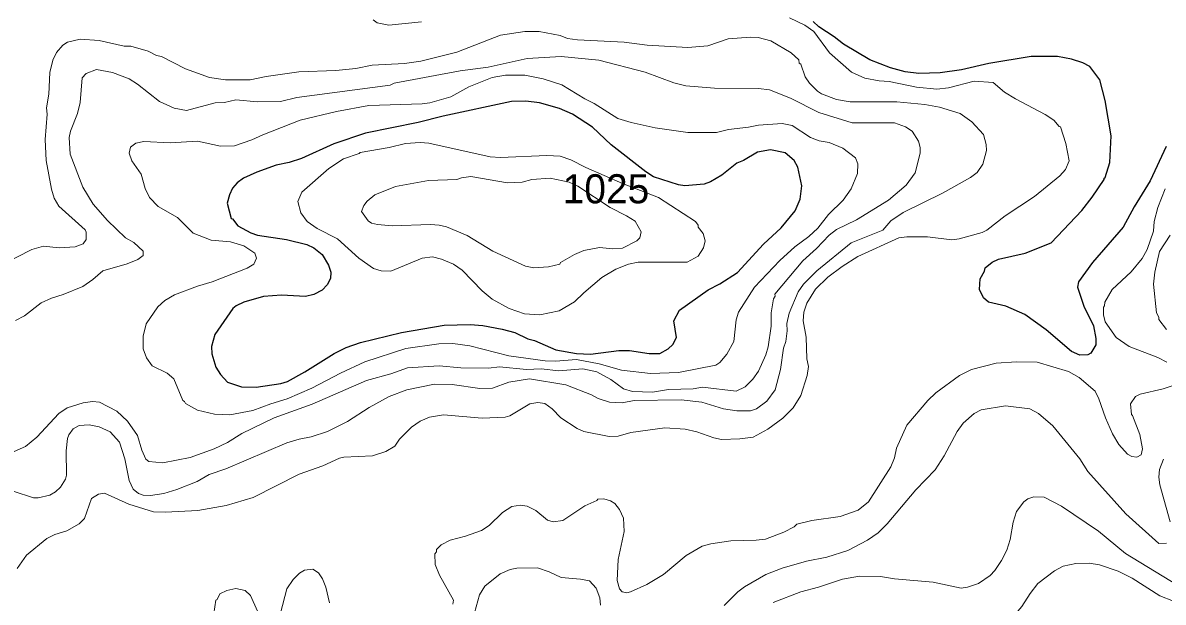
# Model space of a CAD drawing. Extents: x 447.8 to 473.9, y 7733.1 to 7760.8.
# Drawn here: x 469.176 to 472.312, y 7755.382 to 7756.976 of the extents above; entities that cross this region are included whole.
import ezdxf

# ---------------------------------------------------------------- set-up
doc = ezdxf.new("R2010")
doc.units = 0
doc.header["$LTSCALE"] = 0.032
doc.layers.add('1', color=7, linetype='Continuous', lineweight=25)
doc.layers.add('2', color=7, linetype='Continuous', lineweight=13)
doc.layers.add('21', color=7, linetype='Continuous')

msp = doc.modelspace()

# ---------------------------------------------------------------- linework, layer by layer
at = {"layer": '1'}
for points in [[(472.0594, 7756.0718), (471.9898, 7756.1313), (471.9307, 7756.1734), (471.8785, 7756.1964), (471.8309, 7756.2068), (471.8175, 7756.2187), (471.8061, 7756.2423), (471.8084, 7756.2715), (471.8203, 7756.2928), (471.8224, 7756.3018), (471.8413, 7756.3175), (471.8586, 7756.3254), (471.9318, 7756.3423), (472.0034, 7756.3704), (472.0876, 7756.4589), (472.1165, 7756.4956), (472.1489, 7756.5444), (472.1492, 7756.5483), (472.1523, 7756.5496), (472.1652, 7756.5917), (472.1683, 7756.665), (472.1521, 7756.7616), (472.1376, 7756.8188), (472.1101, 7756.855), (472.0906, 7756.8653), (472.0598, 7756.8759), (472.0212, 7756.8826), (471.9484, 7756.8826), (471.8324, 7756.8633), (471.7567, 7756.8459), (471.6983, 7756.8377), (471.6393, 7756.8363), (471.6021, 7756.8411), (471.5614, 7756.8513), (471.5048, 7756.8738), (471.4325, 7756.9169), (471.4068, 7756.9372), (471.3648, 7756.9641), (471.3489, 7756.9792)], [(470.9815, 7756.1847), (471.06, 7756.2408), (471.0926, 7756.2574), (471.141, 7756.289), (471.213, 7756.3666), (471.261, 7756.4114), (471.2996, 7756.4581), (471.3138, 7756.4908), (471.3177, 7756.5275), (471.3068, 7756.5785), (471.2973, 7756.597), (471.2721, 7756.6178), (471.232, 7756.6261), (471.1964, 7756.6198), (471.1578, 7756.5967), (471.1395, 7756.5894), (471.0976, 7756.5568), (471.0666, 7756.5378), (471.049, 7756.5315), (470.9961, 7756.5268), (470.9784, 7756.53), (470.9104, 7756.5519), (470.889, 7756.5655), (470.7939, 7756.6396), (470.7422, 7756.6882), (470.687, 7756.7247), (470.652, 7756.7399), (470.5969, 7756.7553), (470.5591, 7756.76), (470.5199, 7756.7592), (470.3315, 7756.7192), (470.2629, 7756.7012), (470.118, 7756.6722), (470.031, 7756.6429), (469.9424, 7756.6019), (469.9082, 7756.591), (469.8726, 7756.5836), (469.8194, 7756.5643), (469.7831, 7756.5478), (469.7657, 7756.5353), (469.7524, 7756.5205), (469.7441, 7756.5027), (469.7381, 7756.4795), (469.7489, 7756.4376), (469.7527, 7756.4365), (469.7671, 7756.4167), (469.8033, 7756.3979), (469.8215, 7756.3918), (469.9013, 7756.3797), (469.9572, 7756.3657), (469.9765, 7756.3562), (469.9992, 7756.3384), (470.0169, 7756.3085), (470.0232, 7756.2895), (470.0224, 7756.2722), (470.0129, 7756.2545), (469.9987, 7756.2402), (469.9765, 7756.2285), (469.953, 7756.223), (469.8872, 7756.2261), (469.8381, 7756.2225), (469.7837, 7756.207), (469.7623, 7756.1967), (469.7532, 7756.1893), (469.7036, 7756.1182), (469.695, 7756.0851), (469.6954, 7756.0654), (469.7068, 7756.0279), (469.7196, 7756.0077), (469.7389, 7755.9868), (469.7768, 7755.9744), (469.8172, 7755.9729), (469.8858, 7755.9834), (469.9033, 7755.9891), (469.9511, 7756.0153), (470.0316, 7756.066), (470.0646, 7756.0826), (470.1043, 7756.0964), (470.2176, 7756.1236), (470.3342, 7756.1438), (470.4056, 7756.146), (470.4405, 7756.1428), (470.4938, 7756.1331), (470.5287, 7756.1234), (470.5648, 7756.1061), (470.5832, 7756.1018), (470.6413, 7756.076), (470.6986, 7756.0658), (470.7371, 7756.0643), (470.8144, 7756.0739), (470.8445, 7756.0738), (470.8983, 7756.0659), (470.9271, 7756.0659), (470.9507, 7756.0787), (470.9633, 7756.0905)], [(472.3202, 7756.6351), (472.2757, 7756.5412), (472.2317, 7756.4693), (472.2016, 7756.4137), (472.1176, 7756.3165), (472.0787, 7756.2629), (472.0763, 7756.2481), (472.0931, 7756.1963), (472.1201, 7756.1423), (472.1266, 7756.1071)], [(470.9633, 7756.0905), (470.973, 7756.1102), (470.966, 7756.1556), (470.9815, 7756.1847)], [(472.1266, 7756.1071), (472.1264, 7756.0901), (472.1129, 7756.0667), (472.1048, 7756.0626), (472.0821, 7756.0611), (472.0594, 7756.0718)]]:
    msp.add_lwpolyline(points, dxfattribs=at)
at = {"layer": '2'}
for points in [[(470.2723, 7756.9786), (470.1825, 7756.9693), (470.1502, 7756.9755), (470.1389, 7756.9835)], [(472.0289, 7756.6891), (472.0255, 7756.6899), (472.0109, 7756.7079), (471.9868, 7756.7233), (471.9052, 7756.766), (471.8756, 7756.7852), (471.8442, 7756.8111), (471.7922, 7756.8146), (471.7216, 7756.7971), (471.6894, 7756.793), (471.6337, 7756.7986), (471.5579, 7756.8145), (471.5306, 7756.8155), (471.4915, 7756.8232), (471.4547, 7756.8396), (471.3939, 7756.8934), (471.3509, 7756.9521), (471.326, 7756.9688), (471.2842, 7756.9892)], [(469.1181, 7756.3099), (469.2011, 7756.3521), (469.2329, 7756.3608), (469.2759, 7756.3561), (469.32, 7756.359), (469.3418, 7756.3672), (469.3497, 7756.3791), (469.3501, 7756.3999), (469.3474, 7756.4064), (469.2754, 7756.4716), (469.2622, 7756.4935), (469.2545, 7756.5175), (469.2402, 7756.597), (469.2378, 7756.6544), (469.2426, 7756.7247), (469.241, 7756.7416), (469.2473, 7756.7797), (469.2506, 7756.8393), (469.2581, 7756.8725), (469.2684, 7756.8942), (469.2861, 7756.9141), (469.2989, 7756.9223), (469.3334, 7756.9308), (469.3861, 7756.9268), (469.4546, 7756.9114), (469.4726, 7756.9115), (469.5204, 7756.8975), (469.5437, 7756.886), (469.5569, 7756.8826), (469.6236, 7756.8493), (469.6895, 7756.825), (469.7336, 7756.8186), (469.8011, 7756.8186), (469.845, 7756.8281), (469.9348, 7756.841), (470.0368, 7756.8443), (470.0919, 7756.8498), (470.1368, 7756.8586), (470.2258, 7756.8633), (470.2706, 7756.8696), (470.3689, 7756.8946), (470.4893, 7756.9413), (470.5559, 7756.9517), (470.5953, 7756.9517), (470.6533, 7756.9404), (470.6736, 7756.9321), (470.7011, 7756.9284), (470.8296, 7756.9219), (470.8931, 7756.914), (471.0049, 7756.9076), (471.0595, 7756.9125), (471.1152, 7756.9318), (471.1769, 7756.9363), (471.1981, 7756.9348), (471.2323, 7756.9258), (471.2885, 7756.8929), (471.3097, 7756.8738), (471.3107, 7756.8646), (471.3149, 7756.8619), (471.3273, 7756.8268), (471.339, 7756.8094), (471.3606, 7756.7874), (471.3718, 7756.7799), (471.4129, 7756.7649), (471.4511, 7756.7585), (471.579, 7756.7584), (471.6562, 7756.7505), (471.6967, 7756.7433), (471.7534, 7756.7262), (471.7857, 7756.7033), (471.8172, 7756.6683), (471.8252, 7756.6406), (471.8253, 7756.6243), (471.8159, 7756.5868), (471.7998, 7756.5639), (471.7822, 7756.5502), (471.705, 7756.5067), (471.5963, 7756.454), (471.5629, 7756.4311), (471.5406, 7756.4051), (471.4536, 7756.3706), (471.3593, 7756.2933), (471.3229, 7756.2569), (471.3076, 7756.2353), (471.2833, 7756.177), (471.277, 7756.1484), (471.2777, 7756.1285), (471.2737, 7756.0987), (471.2675, 7756.0802), (471.2594, 7756.0221), (471.2449, 7755.9657), (471.2217, 7755.9345), (471.1931, 7755.9133), (471.1771, 7755.908), (471.1388, 7755.908)], [(470.656, 7756.8827), (470.5623, 7756.8771), (470.4551, 7756.8536), (470.3789, 7756.8434), (470.1972, 7756.8092), (470.1857, 7756.8039), (469.9291, 7756.7705), (469.8845, 7756.7593), (469.821, 7756.7585), (469.7616, 7756.764), (469.7305, 7756.7559), (469.7046, 7756.7552), (469.6261, 7756.7344), (469.5917, 7756.741), (469.552, 7756.7588), (469.4916, 7756.8069), (469.4686, 7756.8217), (469.4226, 7756.839), (469.3781, 7756.8473), (469.35, 7756.8361), (469.3394, 7756.8243), (469.3339, 7756.756), (469.3265, 7756.7265), (469.3067, 7756.6776), (469.3035, 7756.6605), (469.306, 7756.614), (469.3405, 7756.5233), (469.3698, 7756.4765), (469.4091, 7756.4316), (469.4585, 7756.3845), (469.4812, 7756.3708), (469.5066, 7756.3476), (469.5068, 7756.3351), (469.492, 7756.3244), (469.4629, 7756.3122), (469.3961, 7756.2936), (469.3682, 7756.2692), (469.3406, 7756.2504), (469.2868, 7756.2283), (469.2544, 7756.2184), (469.226, 7756.2051), (469.1803, 7756.1694), (469.1554, 7756.1566)], [(471.0774, 7756.7954), (470.9993, 7756.8018), (470.9662, 7756.8104), (470.8868, 7756.8396), (470.7594, 7756.873), (470.656, 7756.8827)], [(471.4537, 7756.5187), (471.4708, 7756.5613), (471.4724, 7756.5876), (471.4659, 7756.6044), (471.4308, 7756.6309), (471.3931, 7756.646), (471.366, 7756.6512), (471.3414, 7756.6597), (471.2914, 7756.6927), (471.2637, 7756.6983), (471.1984, 7756.6943), (471.1716, 7756.6885), (471.1167, 7756.6822), (471.0833, 7756.6735), (471.0041, 7756.6735), (470.9143, 7756.6864), (470.8491, 7756.7011), (470.8123, 7756.7126), (470.7473, 7756.754), (470.7216, 7756.766), (470.6584, 7756.8048), (470.6065, 7756.8218), (470.5559, 7756.8313), (470.5035, 7756.8313), (470.4661, 7756.8249), (470.4019, 7756.7995), (470.3526, 7756.7715), (470.2947, 7756.7558), (470.2741, 7756.7529), (470.1272, 7756.748), (470.0381, 7756.732), (469.9387, 7756.708), (469.8358, 7756.6678), (469.8059, 7756.6534), (469.7584, 7756.6374), (469.7191, 7756.636), (469.6565, 7756.6502), (469.5811, 7756.6455), (469.5086, 7756.6486), (469.4869, 7756.6448), (469.4719, 7756.6331), (469.4687, 7756.6167), (469.4758, 7756.596), (469.5014, 7756.5588), (469.512, 7756.52), (469.5246, 7756.495), (469.548, 7756.4699), (469.6014, 7756.4404), (469.644, 7756.3966), (469.6939, 7756.3778), (469.7466, 7756.3735), (469.7838, 7756.3619), (469.8141, 7756.3421), (469.8181, 7756.3281), (469.8108, 7756.312), (469.7932, 7756.3003), (469.6965, 7756.2629), (469.6558, 7756.2509), (469.5932, 7756.2274), (469.5662, 7756.2115), (469.547, 7756.1939), (469.5154, 7756.1475), (469.5071, 7756.1138), (469.5073, 7756.0783), (469.5157, 7756.0541), (469.5312, 7756.0323), (469.5728, 7756.0121), (469.5909, 7755.9965), (469.6156, 7755.9363), (469.6208, 7755.9335), (469.6228, 7755.9281), (469.6566, 7755.9102), (469.7029, 7755.8988), (469.7455, 7755.8969), (469.8088, 7755.9088), (469.8575, 7755.9278), (469.9024, 7755.9414), (469.9707, 7755.9706), (470.0492, 7756.0115), (470.1165, 7756.0428), (470.2294, 7756.0794), (470.3195, 7756.0923), (470.3587, 7756.0931), (470.4052, 7756.0867), (470.5119, 7756.0595), (470.6119, 7756.0461), (470.6405, 7756.045), (470.6986, 7756.049), (470.7611, 7756.0378), (470.8219, 7756.0198), (470.9018, 7756.0105), (470.9784, 7756.0137), (471.0813, 7756.0339), (471.0923, 7756.0415), (471.112, 7756.0637)], [(469.1519, 7755.7963), (469.1832, 7755.8101), (469.2143, 7755.8356), (469.2752, 7755.9004), (469.2981, 7755.9164), (469.3423, 7755.9305), (469.3671, 7755.9337), (469.3868, 7755.932), (469.4344, 7755.9069), (469.4635, 7755.8794), (469.4913, 7755.84), (469.5029, 7755.8002), (469.5145, 7755.7749), (469.5225, 7755.7685), (469.5606, 7755.7653), (469.6357, 7755.7794), (469.7017, 7755.8032), (469.7389, 7755.821), (469.7783, 7755.8456), (469.8675, 7755.8886), (469.9716, 7755.9269), (470.1208, 7755.9912), (470.1878, 7756.0103), (470.234, 7756.0267), (470.3204, 7756.0323), (470.3805, 7756.0267), (470.4564, 7756.0258), (470.4862, 7756.029), (470.5612, 7756.0218), (470.6008, 7756.0241), (470.6498, 7756.0178), (470.7159, 7756.0233), (470.7543, 7756.0153), (470.7931, 7755.9943), (470.8274, 7755.9684), (470.8523, 7755.9613), (470.9073, 7755.9593), (470.9512, 7755.9672), (471.0188, 7755.9689), (471.045, 7755.9737), (471.1377, 7755.9625), (471.1618, 7755.9746), (471.1836, 7755.9951), (471.1992, 7756.017), (471.2192, 7756.0619), (471.2256, 7756.0843), (471.2336, 7756.1413), (471.2337, 7756.1777), (471.2402, 7756.2162), (471.2448, 7756.2232), (471.2436, 7756.2295), (471.321, 7756.3206), (471.3586, 7756.3543), (471.3935, 7756.3917), (471.4133, 7756.4073), (471.4687, 7756.4335), (471.5561, 7756.4875), (471.605, 7756.5286), (471.6299, 7756.5627), (471.6431, 7756.6174), (471.6435, 7756.6326), (471.6385, 7756.6502), (471.6217, 7756.6779), (471.6027, 7756.6894), (471.5732, 7756.7008), (471.4562, 7756.7008), (471.3645, 7756.729), (471.2869, 7756.7687), (471.2293, 7756.7908), (471.1991, 7756.7952), (471.0774, 7756.7954)], [(471.9581, 7756.4976), (472.0278, 7756.5546), (472.0428, 7756.5723), (472.0529, 7756.5958), (472.0441, 7756.6435), (472.0289, 7756.6891)], [(471.2575, 7756.3213), (471.2984, 7756.359), (471.3369, 7756.3876), (471.3617, 7756.4103), (471.3913, 7756.448), (471.4314, 7756.4873), (471.4537, 7756.5187)], [(472.3167, 7756.5187), (472.2966, 7756.4678), (472.287, 7756.4294), (472.2852, 7756.4026), (472.2676, 7756.3518), (472.2537, 7756.327), (472.2234, 7756.2901), (472.1712, 7756.2421), (472.151, 7756.2067), (472.1505, 7756.1972), (472.1475, 7756.1934), (472.1475, 7756.1721), (472.152, 7756.1526), (472.1827, 7756.11), (472.2179, 7756.0848), (472.2968, 7756.0545), (472.3219, 7756.042)], [(469.1603, 7755.4742), (469.1859, 7755.5114), (469.2416, 7755.5572), (469.2641, 7755.5683), (469.2967, 7755.5784), (469.331, 7755.5972), (469.3451, 7755.6116), (469.3646, 7755.6668), (469.3843, 7755.6789), (469.4009, 7755.6819), (469.467, 7755.6514), (469.5355, 7755.6305), (469.5687, 7755.6291), (469.6574, 7755.6338), (469.7351, 7755.6475), (469.8091, 7755.6693), (469.9358, 7755.7343), (470.0008, 7755.7564), (470.0468, 7755.7777), (470.0587, 7755.7807), (470.1371, 7755.7846), (470.1743, 7755.7959), (470.1989, 7755.8112), (470.2121, 7755.83), (470.2448, 7755.8632), (470.2686, 7755.8799), (470.2942, 7755.8903), (470.3324, 7755.8967), (470.4394, 7755.888), (470.5019, 7755.8903), (470.5155, 7755.8945), (470.5697, 7755.9278), (470.5924, 7755.9312), (470.6114, 7755.9279), (470.6312, 7755.9133), (470.6552, 7755.8893), (470.7005, 7755.8595), (470.7186, 7755.8511), (470.7884, 7755.8376), (470.8133, 7755.8382), (470.8474, 7755.8486), (470.9413, 7755.8615), (470.9968, 7755.8574), (471.0297, 7755.8503), (471.0756, 7755.834), (471.0967, 7755.8295), (471.1474, 7755.8312), (471.1839, 7755.8359), (471.2243, 7755.8576), (471.2656, 7755.8884), (471.2946, 7755.916), (471.3148, 7755.9499), (471.333, 7756.0057), (471.3363, 7756.0303), (471.3315, 7756.0516), (471.3298, 7756.1112), (471.3219, 7756.1557), (471.3235, 7756.1793), (471.3321, 7756.2042), (471.3559, 7756.2424), (471.3898, 7756.2759), (471.429, 7756.3056), (471.4717, 7756.3328), (471.5844, 7756.384), (471.6065, 7756.3865), (471.6637, 7756.3865), (471.73, 7756.3786), (471.7503, 7756.3809), (471.8137, 7756.3984), (471.8271, 7756.4051), (471.8771, 7756.4443), (471.9581, 7756.4976)], [(472.3208, 7756.1316), (472.2998, 7756.1592), (472.2997, 7756.1657), (472.2934, 7756.1777), (472.2854, 7756.257), (472.2886, 7756.2898), (472.3014, 7756.3468), (472.3307, 7756.3911)], [(471.112, 7756.0637), (471.131, 7756.0987), (471.1375, 7756.1584), (471.1439, 7756.1795), (471.1874, 7756.2481), (471.2575, 7756.3213)], [(472.2549, 7755.8038), (472.2509, 7755.7872), (472.2393, 7755.7806), (472.225, 7755.7823), (472.2135, 7755.7892), (472.1894, 7755.8151), (472.1722, 7755.8446), (472.1528, 7755.8891), (472.1349, 7755.941), (472.1241, 7755.9624), (472.0808, 7755.9997), (472.0513, 7756.0161), (471.9651, 7756.0418), (471.9086, 7756.0426), (471.8525, 7756.0394), (471.7848, 7756.0216), (471.7518, 7756.0051), (471.6863, 7755.9573), (471.6647, 7755.9366), (471.6063, 7755.8691), (471.5785, 7755.8056), (471.5724, 7755.7785), (471.5625, 7755.7543), (471.5014, 7755.6579), (471.4727, 7755.6351), (471.4232, 7755.6178), (471.3452, 7755.6064), (471.3042, 7755.5963), (471.2968, 7755.589), (471.2683, 7755.5742), (471.218, 7755.5553), (471.1927, 7755.5521), (471.1227, 7755.5504), (471.0673, 7755.5425), (471.0442, 7755.5359), (470.9999, 7755.5105), (470.9374, 7755.4576), (470.8916, 7755.4307), (470.847, 7755.4101), (470.8365, 7755.4078), (470.8241, 7755.41), (470.8162, 7755.4187), (470.8105, 7755.4411), (470.8129, 7755.4995), (470.8296, 7755.5761), (470.828, 7755.6126), (470.8164, 7755.6364), (470.804, 7755.6529), (470.7917, 7755.6604), (470.7739, 7755.6658), (470.7569, 7755.6649), (470.7542, 7755.6612), (470.721, 7755.6465), (470.6604, 7755.6062), (470.6338, 7755.6026), (470.6187, 7755.607), (470.5863, 7755.6336), (470.5624, 7755.646), (470.5447, 7755.649), (470.5209, 7755.6452), (470.4951, 7755.6286), (470.458, 7755.5925), (470.4376, 7755.5789), (470.3928, 7755.563), (470.3513, 7755.5522), (470.3266, 7755.5394), (470.3138, 7755.5268), (470.3132, 7755.5206), (470.3086, 7755.5147), (470.3095, 7755.4851), (470.322, 7755.4564), (470.3598, 7755.3873), (470.3583, 7755.3761)], [(470.8236, 7755.9305), (470.7893, 7755.9321), (470.7582, 7755.9422), (470.7399, 7755.952), (470.6693, 7755.9801), (470.5691, 7755.996), (470.5126, 7755.9866), (470.467, 7755.9705), (470.433, 7755.9697), (470.3564, 7755.981), (470.3083, 7755.9817), (470.232, 7755.9657), (470.183, 7755.9478), (470.1281, 7755.9171), (470.0686, 7755.8785), (470.0133, 7755.8517), (469.9685, 7755.8366), (469.9358, 7755.8304), (469.9021, 7755.82), (469.7338, 7755.7487), (469.6885, 7755.7326), (469.655, 7755.7138), (469.5994, 7755.6913), (469.5638, 7755.6805), (469.527, 7755.6756), (469.5067, 7755.6764), (469.4937, 7755.6807), (469.4795, 7755.693), (469.4684, 7755.7162), (469.4563, 7755.776), (469.4417, 7755.822), (469.4157, 7755.8502), (469.3862, 7755.864), (469.3582, 7755.8694), (469.3311, 7755.8678), (469.3146, 7755.8587), (469.3027, 7755.8422), (469.299, 7755.8321), (469.2947, 7755.7985), (469.2962, 7755.7316), (469.2937, 7755.7201), (469.28, 7755.6977), (469.266, 7755.6853), (469.2505, 7755.6763), (469.2181, 7755.6691), (469.205, 7755.6692), (469.1492, 7755.6876)], [(472.3421, 7755.9787), (472.3114, 7755.9685), (472.2484, 7755.9544), (472.2359, 7755.9479)], [(471.1388, 7755.908), (471.1029, 7755.9137), (471.0426, 7755.9321), (470.9859, 7755.9384), (470.8566, 7755.9368), (470.8236, 7755.9305)], [(472.2359, 7755.9479), (472.2216, 7755.9275), (472.2245, 7755.8979), (472.2276, 7755.8957), (472.2474, 7755.8429), (472.2549, 7755.8038)], [(471.1042, 7755.3728), (471.1423, 7755.4101), (471.1605, 7755.424), (471.2187, 7755.4583), (471.2635, 7755.4749), (471.3311, 7755.4943), (471.3869, 7755.5057), (471.4444, 7755.5243), (471.4985, 7755.5522), (471.5276, 7755.5727), (471.5523, 7755.5972), (471.6318, 7755.6905), (471.6843, 7755.7455), (471.7095, 7755.7839), (471.7449, 7755.8515), (471.762, 7755.8743), (471.7918, 7755.9009), (471.8115, 7755.9113), (471.8781, 7755.9223), (471.9448, 7755.9137)], [(471.9448, 7755.9137), (471.9685, 7755.9011), (472.0077, 7755.8673), (472.0822, 7755.7759), (472.1047, 7755.7414), (472.2092, 7755.6249)], [(472.3311, 7755.603), (472.3021, 7755.7043), (472.2998, 7755.7257), (472.3015, 7755.7467), (472.312, 7755.7752)], [(472.134, 7755.5772), (472.032, 7755.6458), (471.9845, 7755.6704), (471.9561, 7755.6714), (471.9391, 7755.6658), (471.9284, 7755.6575), (471.908, 7755.6309), (471.8991, 7755.602), (471.891, 7755.5539), (471.8814, 7755.5251), (471.8673, 7755.4965), (471.8487, 7755.4689), (471.8354, 7755.4556), (471.8033, 7755.4336), (471.7733, 7755.423), (471.756, 7755.4207), (471.679, 7755.4367), (471.5732, 7755.4463), (471.5347, 7755.4527), (471.4767, 7755.4534), (471.4295, 7755.4447), (471.3642, 7755.4232), (471.3148, 7755.4106), (471.2396, 7755.3809)], [(472.2092, 7755.6249), (472.2996, 7755.5428), (472.3209, 7755.5438)], [(472.451, 7755.3997), (472.4365, 7755.3982), (472.3889, 7755.4112), (472.3505, 7755.429), (472.2075, 7755.5158), (472.134, 7755.5772)], [(470, 7755.4462), (469.9888, 7755.4621), (469.9736, 7755.4726), (469.9502, 7755.4696), (469.9369, 7755.4614), (469.9195, 7755.4437)], [(470.4137, 7755.336), (470.4319, 7755.4023), (470.4466, 7755.4254), (470.4885, 7755.46), (470.5157, 7755.472), (470.5344, 7755.4751), (470.591, 7755.476), (470.6231, 7755.4653), (470.656, 7755.4499), (470.7097, 7755.4454), (470.7338, 7755.4407), (470.7527, 7755.4203), (470.7629, 7755.394), (470.764, 7755.3735)], [(472.3395, 7755.3844), (472.3024, 7755.3993), (472.2267, 7755.4474), (472.1878, 7755.4669), (472.1362, 7755.4847), (472.1077, 7755.4888), (472.0714, 7755.4879), (472.0362, 7755.4812), (472.0131, 7755.468), (471.9669, 7755.4332)], [(469.9195, 7755.4437), (469.9021, 7755.4187), (469.8845, 7755.3513)], [(470.0191, 7755.3796), (470.0092, 7755.4227), (470, 7755.4462)], [(471.9669, 7755.4332), (471.9457, 7755.4059), (471.9232, 7755.3696), (471.8956, 7755.3378), (471.8664, 7755.3133), (471.8415, 7755.3005)], [(469.8214, 7755.357), (469.802, 7755.3997), (469.7874, 7755.414), (469.7619, 7755.419), (469.737, 7755.4143), (469.7175, 7755.4046), (469.7105, 7755.3895), (469.7071, 7755.3877), (469.7011, 7755.3507)]]:
    msp.add_lwpolyline(points, dxfattribs=at)
for points in [[(471.0025, 7756.3167), (471.0329, 7756.3334), (471.0478, 7756.3563), (471.0525, 7756.3761), (471.0465, 7756.3963), (471.0326, 7756.4138), (471.0331, 7756.4193), (471.026, 7756.4289), (470.9242, 7756.4954), (470.8253, 7756.5333), (470.7236, 7756.5774), (470.6825, 7756.5988), (470.6533, 7756.6085), (470.6172, 7756.6102), (470.4892, 7756.6046), (470.4606, 7756.607), (470.2923, 7756.6447), (470.2682, 7756.6462), (470.2282, 7756.6438), (470.1832, 7756.633), (470.1034, 7756.6191), (470.1007, 7756.6157), (470.0579, 7756.601), (470.0171, 7756.575), (469.9431, 7756.5096), (469.9321, 7756.4842), (469.9402, 7756.4524), (469.9578, 7756.4289), (469.9854, 7756.4094), (470.0415, 7756.381), (470.1002, 7756.3284), (470.1406, 7756.2998), (470.1611, 7756.2932), (470.1874, 7756.292), (470.2737, 7756.328), (470.3022, 7756.332), (470.3276, 7756.3256), (470.3602, 7756.3118), (470.3838, 7756.2953), (470.4386, 7756.2381), (470.4663, 7756.2149), (470.5136, 7756.1893), (470.5555, 7756.1753), (470.5977, 7756.172), (470.6504, 7756.1831), (470.6928, 7756.2076), (470.7185, 7756.233), (470.7682, 7756.2747), (470.8062, 7756.2978), (470.8417, 7756.3119), (470.8675, 7756.3167)], [(470.8643, 7756.3754), (470.8729, 7756.3845), (470.876, 7756.4007), (470.8593, 7756.4297), (470.8361, 7756.445), (470.7912, 7756.4674), (470.7025, 7756.5258), (470.6778, 7756.5373), (470.6264, 7756.5484), (470.5759, 7756.5446), (470.5491, 7756.5373), (470.5087, 7756.5357), (470.4077, 7756.5524), (470.3824, 7756.5492), (470.3695, 7756.5445), (470.2912, 7756.5422), (470.2003, 7756.5253), (470.1438, 7756.5021), (470.1226, 7756.4849), (470.114, 7756.4726), (470.1075, 7756.4563), (470.1252, 7756.4307), (470.1351, 7756.4248), (470.1511, 7756.4207), (470.1911, 7756.4169), (470.297, 7756.4209), (470.3205, 7756.4192), (470.3412, 7756.4141), (470.3978, 7756.3909), (470.4679, 7756.3478), (470.5583, 7756.306), (470.5809, 7756.3017), (470.6216, 7756.304), (470.6522, 7756.3119), (470.6544, 7756.3158), (470.6933, 7756.3383), (470.7181, 7756.349), (470.762, 7756.3576), (470.7985, 7756.3537), (470.8245, 7756.3552)]]:
    msp.add_lwpolyline(points, close=True, dxfattribs=at)

# ---------------------------------------------------------------- texts
at = {"layer": '21'}
msp.add_text('1025', height=0.08, dxfattribs=at).set_placement((470.6604, 7756.479))

doc.saveas('drawing.dxf')
